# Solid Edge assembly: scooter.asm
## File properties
Title: scooter
Author: Stella-Marii
Template: Iso Metric Assembly.asm
Last saved by: Stella-Marii
Revision: 83
Application: Solid Edge
Username: Stella-Marii
Document Number: 01
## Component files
hendus.psm
hendus kate.psm
aluse esimene kate.psm
esiratta hoidja.psm
ratas.par
aluse tagumine kate.psm
alus.par
mutter.par
rehv.par
polt.par
tagaratta hoidja.par
poritiib tagumine.par
poritiib esimene.par
lambikate.par
raami alumine toru.par
laadimisjupp.par
raami alumise toru kate.par
kell paigal osa.par
lenksu-ratta toru.par
kell liikuv osa.par
torudevaheline tugevdus.psm
gaas.par
lenksu-ratta sisemine toru.par
toru laager.psm
pidurihoidja.par
lenksu alumine toru.par
lenks.par
epide.par
pidur.par
pidurimumm.par
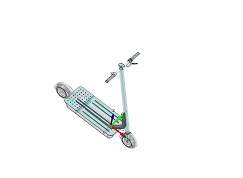
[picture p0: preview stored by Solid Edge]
